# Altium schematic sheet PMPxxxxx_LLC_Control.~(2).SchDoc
size 431 x 279 mm; Date: Not shown in title block; ApprovedBy: Not shown in title block; CheckedBy: Not shown in title block; Author: Not shown in title block; CompanyName: Not shown in title block; Engineer: Not shown in title block; Organization: Not shown in title block; Address1: Not shown in title block; Address2: Not shown in title block; Address3: Not shown in title block; Address4: Not shown in title block; DocumentNumber: 1; Revision: Use project parameter SCH_Rev; SheetNumber: 4; SheetTotal: 4; PageSetup: Record=PageOptions¦CenterHorizontal=True¦CenterVertical=True¦PrintScale=1.00¦XCorrection=1.00¦YCorrection=1.00¦PrintKind=0¦BorderSize=5000000¦LeftOffset=0¦BottomOffset=0¦Orientation=2¦PaperLength=1000¦PaperWidth=1000¦Scale=100¦PaperSource=15¦PrintQuality=600¦MediaType=1¦DitherType=10¦PaperKind=Letter¦PrintScaleMode=1
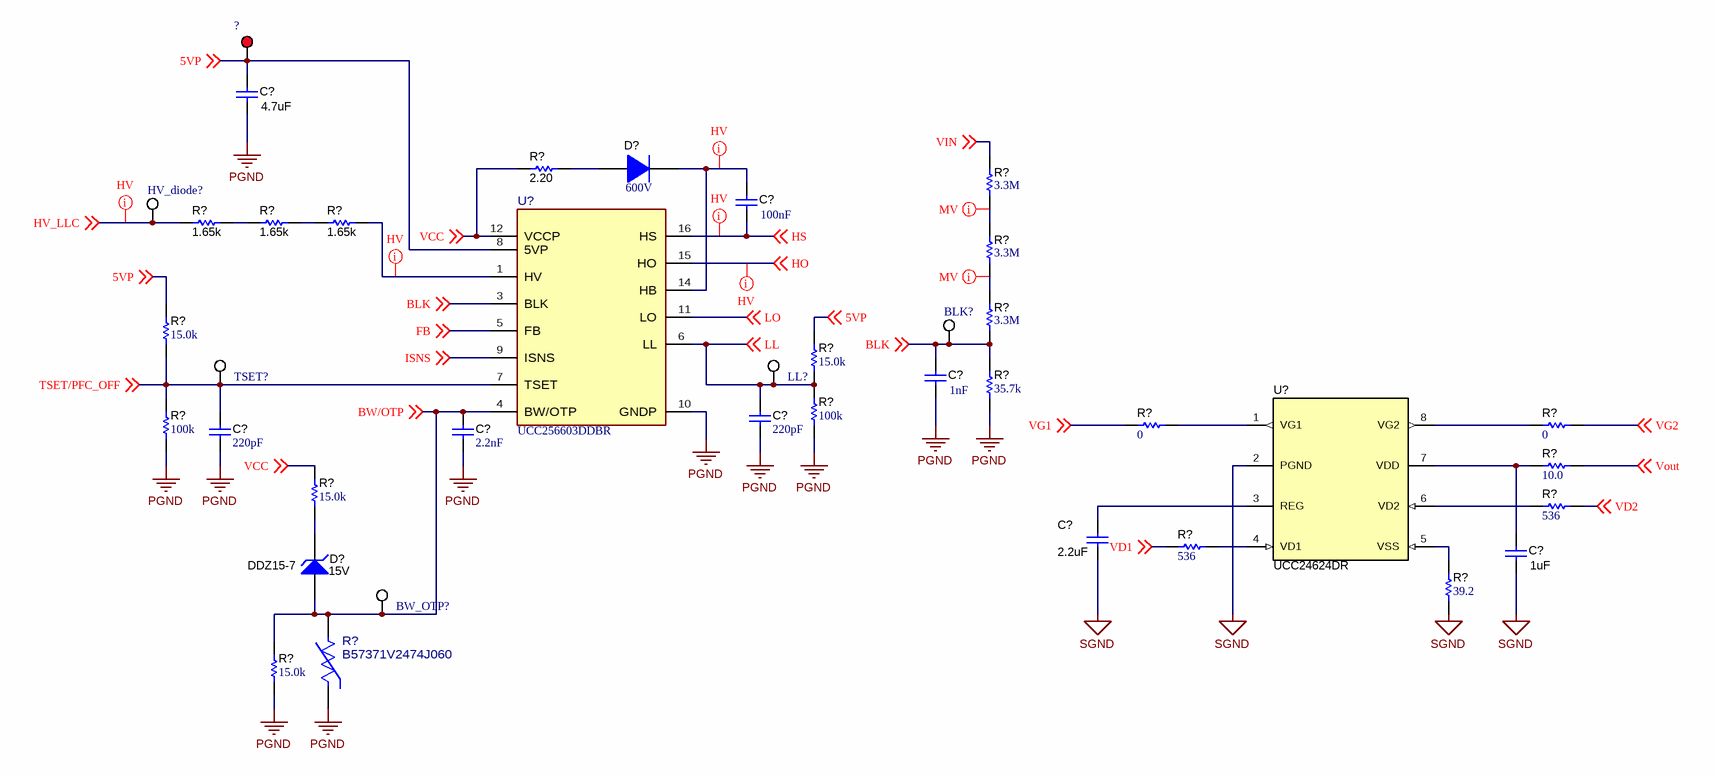
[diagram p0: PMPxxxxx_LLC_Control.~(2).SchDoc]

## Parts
(Parts that share a designator on the sheet are numbered #1, #2 ... from top to bottom, then left to right.)
?  5010  [Keystone5010]  (value not drawn)
BLK?  5012  [Keystone5012]  (value not drawn)
BW_OTP?  5012  [Keystone5012]  (value not drawn)
C?#1  ValueDisplayed: 4.7uF  [1206L]  (hidden comment: C3216X7R1E475K085AB)
C?#2  Cap_F: 100nF  [1206_180L]  (hidden comment: GRM31C5C1E104JA01L)
C?#3  Cap_F: 1nF  [0402L]  (hidden comment: 04025C102JAT2A)
C?#4  Cap_F: 220pF  [0603]  (hidden comment: C0603X221K5RACTU)
C?#5  Cap_F: 220pF  [0603]  (hidden comment: C0603X221K5RACTU)
C?#6  Cap_F: 2.2nF  [0603]  (hidden comment: C0603X222K5RACTU)
C?#7  ValueDisplayed: 2.2uF  [0805L]  (hidden comment: C2012X7R1V225K085AC)
C?#8  ValueDisplayed: 1uF  [0603L]  (hidden comment: GRM188R71C105KE15D)
D?#1  Vr_V: 600V  [SMAF]  (hidden comment: ES1JAF)
D?#2  DDZ15-7  value 15V  [SOD-123]
HV_diode?  5012  [Keystone5012]  (value not drawn)
LL?  5012  [Keystone5012]  (value not drawn)
R?#1  ValueDisplayed: 2.20  [0603L]  (hidden comment: ERJ-3RQF2R2V)
R?#2  Res_ohm: 3.3M  [FP-KTR18EZPF3304_1206-MFG]  (hidden comment: KTR18EZPF3304)
R?#3  ValueDisplayed: 1.65k  [1206L]  (hidden comment: CRCW12061K65FKEA)
R?#4  ValueDisplayed: 1.65k  [1206L]  (hidden comment: CRCW12061K65FKEA)
R?#5  ValueDisplayed: 1.65k  [1206L]  (hidden comment: CRCW12061K65FKEA)
R?#6  Res_ohm: 3.3M  [FP-KTR18EZPF3304_1206-MFG]  (hidden comment: KTR18EZPF3304)
R?#7  Res_ohm: 3.3M  [FP-KTR18EZPF3304_1206-MFG]  (hidden comment: KTR18EZPF3304)
R?#8  ValueDisplayed: 15.0k  [0603]  (hidden comment: RT0603BRD0715KL)
R?#9  ValueDisplayed: 15.0k  [0603]  (hidden comment: RT0603BRD0715KL)
R?#10  ValueDisplayed: 35.7k  [0603]  (hidden comment: RT0603BRD0735K7L)
R?#11  ValueDisplayed: 100k  [0603]  (hidden comment: RT0603BRD07100KL)
R?#12  ValueDisplayed: 100k  [0603]  (hidden comment: RT0603BRD07100KL)
R?#13  ValueDisplayed: 0  [0603L]  (hidden comment: RC0603JR-070RL)
R?#14  ValueDisplayed: 0  [0603L]  (hidden comment: RC0603JR-070RL)
R?#15  ValueDisplayed: 10.0  [0603L]  (hidden comment: RC0603FR-0710RL)
R?#16  ValueDisplayed: 15.0k  [0603]  (hidden comment: RG1608P-153-B-T5)
R?#17  ValueDisplayed: 536  [0603L]  (hidden comment: RT0603BRD07536RL)
R?#18  ValueDisplayed: 536  [0603L]  (hidden comment: RT0603BRD07536RL)
R?#19  ValueDisplayed: 39.2  [0603L]  (hidden comment: RC0603FR-0739R2L)
R?#20  ValueDisplayed: 15.0k  [0603]  (hidden comment: RG1608P-153-B-T5)
R?#21  B57371V2474J060  [FP-B57371V2474J060_0603-MFG]
TSET?  5012  [Keystone5012]  (value not drawn)
U?#1  UCC256603DDBR  [DDB0014A-MFG]
U?#2  UCC24624DR  [D0008A_N]

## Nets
PGND: C?#1.2 C?#3.2 C?#4.2 C?#5.2 C?#6.2 R?#10.1 R?#11.1 R?#12.1 R?#20.1 R?#21.1 U?#1.10(GNDP)
SGND: C?#7.2 C?#8.2 R?#19.2 U?#2.2(PGND)
5VP: ?.1 C?#1.1 R?#8.2 R?#9.2 U?#1.8(5VP) ; off-sheet 5VP
BLK: BLK?.1 C?#3.1 R?#7.1 R?#10.2 U?#1.3(BLK) ; off-sheet BLK
BW/OTP: BW_OTP?.1 C?#6.1 D?#2.2(A) R?#20.2 R?#21.2 U?#1.4(BW/OTP) ; off-sheet BW/OTP
FB: U?#1.5(FB) ; off-sheet FB
HO: U?#1.15(HO) ; off-sheet HO
HS: C?#2.2 U?#1.16(HS) ; off-sheet HS
HV_LLC: HV_diode?.1 R?#3.1 ; off-sheet HV_LLC
ISNS: U?#1.9(ISNS) ; off-sheet ISNS
LL: C?#4.1 LL?.1 R?#9.1 R?#11.2 U?#1.6(LL) ; off-sheet LL
LO: U?#1.11(LO) ; off-sheet LO
TSET/PFC_OFF: C?#5.1 R?#8.1 R?#12.2 TSET?.1 U?#1.7(TSET) ; off-sheet TSET/PFC_OFF
VCC: R?#1.1 R?#16.2 U?#1.12(VCCP) ; off-sheet VCC
VD1: R?#18.2 ; off-sheet VD1
VD2: R?#17.1 ; off-sheet VD2
VG1: R?#13.1 ; off-sheet VG1
VG2: R?#14.2 ; off-sheet VG2
VIN: R?#2.2 ; off-sheet VIN
Vout: R?#15.2 ; off-sheet Vout
NetC?#2_1: C?#2.1 D?#1.1(K) U?#1.14(HB)
NetC?#7_1: C?#7.1 U?#2.3(REG)
NetC?#8_1: C?#8.1 R?#15.1 U?#2.7(VDD)
NetD?#1_2: D?#1.2(A) R?#1.2
NetD?#2_1: D?#2.1(K) R?#16.1
NetR?#2_1: R?#2.1 R?#6.2
NetR?#3_2: R?#3.2 R?#4.1
NetR?#4_2: R?#4.2 R?#5.1
NetR?#5_2: R?#5.2 U?#1.1(HV)
NetR?#6_1: R?#6.1 R?#7.2
NetR?#13_2: R?#13.2 U?#2.1(VG1)
NetR?#14_1: R?#14.1 U?#2.8(VG2)
NetR?#17_2: R?#17.2 U?#2.6(VD2)
NetR?#18_1: R?#18.1 U?#2.4(VD1)
NetR?#19_1: R?#19.1 U?#2.5(VSS)

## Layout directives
net class MV: NetR?#2_1, NetR?#6_1
net class HV: HO, HS, HV_LLC, NetC?#2_1, NetR?#5_2

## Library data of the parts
? = CMP-0055147-2: Test Point, Multipurpose, Red, TH; Manufacturer: Keystone Electronics; CNHeader: FALSE; Green_Lifecycle: Active; Green_REACh: Passed; ContactFinish: Silver; CT: TRUE
BLK? BW_OTP? HV_diode? LL? TSET? = CMP-0055149-2: Test Point, Multipurpose, White, TH; Manufacturer: Keystone Electronics; CNHeader: FALSE; Green_Lifecycle: Active; Green_REACh: Passed; ContactFinish: Silver; CT: TRUE
C?#1 = CMP-0008693-2: CAP, CERM, 4.7 uF, 25 V, +/- 10%, X7R, 1206; Manufacturer: TDK; TaMin_C: -55°C; Polarized: N; SizeAreaWB_mm2: 10.92; Value1: Unknown; U/M: EA; Value: 4.7uF; TaMax_C: 125°C; SizeZ_mm: 1.35; SizeX_mm: 3.2; SizeY_mm: 1.6; Cap_Case: 1206; Value2: 25V; SizeArea_mm2: 5.12; CompType: Capacitor; Cap_F: 4.7µF; AEC Category: Q200
C?#2 = CMP-0064950-2: CAP, CERM, 0.1 uF, 25 V,+/- 5%, C0G/NP0, 1206; Manufacturer: MuRata; TaMin_C: -55°C; Polarized: N; SizeAreaWB_mm2: 10.92; Value1: Unknown; U/M: EA; Value: 0.1uF; TaMax_C: 125°C; SizeZ_mm: 1.8; SizeX_mm: 3.2; SizeY_mm: 1.6; Cap_Case: 1206; Value2: 25V; SizeArea_mm2: 5.12; AEC Category: Q200
C?#3 = CMP-0861060-1: CAP, CERM, 1000 pF, 50 V,+/- 5%, X7R, 0402; Manufacturer: AVX; Value2: 50V; SizeY_mm: 0.5; AEC Category: Q200; Polarized: N; Green_Lifecycle: Active; SizeAreaWB_mm2: 3; ValueDisplayed: 1000pF; Cap_Case: 0402; Value: 1000pF; TaMin_C: -55°C; U/M: EA; Green_REACh: Passed; SizeZ_mm: 0.6; SizeX_mm: 1; TaMax_C: 125°C
C?#4 C?#5 = CMP-0006982-4: CAP, CERM, 220 pF, 50 V, +/- 10%, X7R, 0603; Manufacturer: Kemet; TaMin_C: -55°C; Polarized: N; SizeAreaWB_mm2: 4.68; Value1: Unknown; U/M: EA; Value: 220pF; TaMax_C: 125°C; SizeZ_mm: 1; SizeX_mm: 1.6; SizeY_mm: 0.8; Value2: 50V; SizeArea_mm2: 1.28; AEC Category: Q200
C?#6 = CMP-0006983-4: CAP, CERM, 2200 pF, 50 V, +/- 10%, X7R, 0603; Manufacturer: Kemet; TaMin_C: -55°C; Polarized: N; SizeAreaWB_mm2: 4.68; Value1: Unknown; U/M: EA; Value: 2200pF; TaMax_C: 125°C; SizeZ_mm: 1; SizeX_mm: 1.6; SizeY_mm: 0.8; Value2: 50V; SizeArea_mm2: 1.28; AEC Category: Q200
C?#7 = CMP-0007883-2: CAP, CERM, 2.2 uF, 35 V, +/- 10%, X7R, 0805; Manufacturer: TDK; TaMin_C: -55°C; Polarized: N; SizeAreaWB_mm2: 6.75; Value1: Unknown; U/M: EA; Value: 2.2uF; TaMax_C: 125°C; SizeZ_mm: 1.45; SizeX_mm: 2; SizeY_mm: 1.25; Cap_Case: 0805; Value2: 35V; SizeArea_mm2: 2.5; CompType: Capacitor; Cap_F: 2.2µF; AEC Category: Q200
C?#8 = CMP-0007380-4: CAP, CERM, 1 uF, 16 V, +/- 10%, X7R, 0603; Manufacturer: MuRata; TaMin_C: -55°C; Polarized: N; SizeAreaWB_mm2: 4.68; Value1: Unknown; U/M: EA; Value: 1uF; TaMax_C: 125°C; SizeZ_mm: 1; SizeX_mm: 1.6; SizeY_mm: 0.8; Cap_Case: 0603; Value2: 16V; SizeArea_mm2: 1.28; CompType: Capacitor; Cap_F: 1µF; AEC Category: Q200
D?#1 = CMP-0029162-2: Diode, Ultrafast, 600 V, 1 A, AEC-Q101, SMAF; Manufacturer: Fairchild Semiconductor; Io_A: 1A; Green_Lifecycle: Not Set; SizeAreaWB_mm2: 19.95; Green_REACh: Incomplete; TJmax_C: 150°C; Value: 600V; SizeZ_mm: 1; SizeX_mm: 4.7; SizeY_mm: 2.5; Vf_V: 1.7V; SizeArea_mm2: 11.75; AEC Qualified: Y; AEC Category: Q101
D?#2 = CMP-0085135-1: Diode, Zener, 15 V, 500 mW, SOD-123; Manufacturer: Diodes Inc.; SizeAreaWB_mm2: 13.095; SizeArea_mm2: 6.545; SizeY_mm: 1.7; AEC Qualified: N; SizeZ_mm: 1.35; Value1: 0.5W; SizeX_mm: 3.85; Power_W: 500mW; RJA_CperW: 425; AEC Category: Q101
R?#1 = CMP-0022711-2: RES, 2.20, 1%, 0.1 W, 0603; Manufacturer: Panasonic; Power_W: 100mW; TempCo: 200 ppm/C; Value_Code: 2R20; U/M: EA; Value: 2.20; Res_ohm: 2.2; SizeX_mm: 1.6; SizeY_mm: 0.8; SizeZ_mm: 1; Value2: 0.1W; SizeArea_mm2: 1.28; CompType: Resistor; AEC Category: Q200
R?#2 R?#6 R?#7 = CMP-0087456-2: 3.3 MOhms ±1% 0.25W, 1/4W Chip Resistor 1206 (3216 Metric) Automotive AEC-Q200, High Voltage Thick Film; Manufacturer: Rohm Semiconductor; AEC Qualified: Yes; Power_W: 250mW; SizeZ_mm: 0.65mm; AEC Grade: Grade 0; TempCo: 100ppm/°C; VDC_V: 500V
R?#3-R?#5 = CMP-0016708-3: RES, 1.65 k, 1%, 0.25 W, AEC-Q200 Grade 0, 1206; Manufacturer: Vishay-Dale; Power_W: 250mW; TempCo: 100 ppm/C; Value_Code: 1k65; Value: 1.65k; EIA_Code: E96; SizeX_mm: 3.2; SizeY_mm: 1.6; SizeZ_mm: 1.35; Value2: 0.25W; SizeArea_mm2: 5.12; CompType: Resistor; AEC Qualified: Y; VDC_V: 200V; AEC Category: Q200; AEC Grade: 0
R?#8 R?#9 = CMP-0023780-3: RES, 15.0 k, 0.1%, 0.1 W, 0603; Manufacturer: Yageo America; Power_W: 100mW; TempCo: 25 ppm/C; Value_Code: 15k0; U/M: EA; Value: 15.0k; EIA_Code: E192; Res_ohm: 15k; SizeX_mm: 1.6; SizeY_mm: 0.8; SizeZ_mm: 1; Value2: 0.1W; SizeArea_mm2: 1.28; VDC_V: 75V; AEC Category: Q200
R?#10 = CMP-0024147-3: RES, 35.7 k, 0.1%, 0.1 W, 0603; Manufacturer: Yageo America; Power_W: 100mW; TempCo: 25 ppm/C; Value_Code: 35k7; U/M: EA; Value: 35.7k; EIA_Code: E192; SizeX_mm: 1.6; SizeY_mm: 0.8; SizeZ_mm: 1; Value2: 0.1W; SizeArea_mm2: 1.28; VDC_V: 75V; AEC Category: Q200
R?#11 R?#12 = CMP-0023630-3: RES, 100 k, 0.1%, 0.1 W, 0603; Manufacturer: Yageo America; Power_W: 100mW; TempCo: 25 ppm/C; U/M: EA; Value: 100k; EIA_Code: E192; SizeX_mm: 1.6; SizeY_mm: 0.8; SizeZ_mm: 1; Value2: 0.1W; SizeArea_mm2: 1.28; VDC_V: 75V; AEC Category: Q200
R?#13 R?#14 = CMP-0025885-5: RES, 0, 5%, 0.1 W, 0603; Manufacturer: Yageo; Power_W: 100mW; TempCo: 200 ppm/C; Value_Code: 0000; Value: 0; EIA_Code: E24; SizeX_mm: 1.6; SizeZ_mm: 1; Value2: 0.1W; SizeArea_mm2: 1.28; AEC Qualified: N; VDC_V: 75V; AEC Category: Q200; SizeY_mm: 0.8; SizeAreaWB_mm2: 4.68
R?#15 = CMP-0022751-4: RES, 10.0, 1%, 0.1 W, 0603; Manufacturer: Yageo; Power_W: 100mW; TempCo: 100 ppm/C; Value_Code: 10R0; Value: 10.0; EIA_Code: E96; Res_ohm: 10; SizeX_mm: 1.6; SizeY_mm: 0.8; SizeZ_mm: 1; Value2: 0.1W; SizeArea_mm2: 1.28; AEC Qualified: N; VDC_V: 75V; AEC Category: Q200; SizeAreaWB_mm2: 4.68
R?#16 R?#20 = CMP-0023441-3: RES, 15.0 k, 0.1%, 0.1 W, 0603; Manufacturer: Susumu Co Ltd; Power_W: 100mW; TempCo: 25 ppm/C; Value_Code: 15k0; U/M: EA; Value: 15.0k; EIA_Code: E192; Res_ohm: 15k; SizeX_mm: 1.6; SizeY_mm: 0.8; SizeZ_mm: 1; Value2: 0.1W; SizeArea_mm2: 1.28; VDC_V: 75V; AEC Category: Q200
R?#17 R?#18 = CMP-0024324-2: RES, 536, 0.1%, 0.1 W, 0603; Manufacturer: Yageo America; Power_W: 100mW; TempCo: 25 ppm/C; Value_Code: 536R; U/M: EA; Value: 536; EIA_Code: E192; SizeX_mm: 1.6; SizeY_mm: 0.8; SizeZ_mm: 1; Value2: 0.1W; SizeArea_mm2: 1.28; VDC_V: 75V; AEC Category: Q200
R?#19 = CMP-0023074-4: RES, 39.2, 1%, 0.1 W, 0603; Manufacturer: Yageo; Power_W: 100mW; TempCo: 100 ppm/C; Value_Code: 39R2; Value: 39.2; EIA_Code: E96; SizeX_mm: 1.6; SizeY_mm: 0.8; SizeZ_mm: 1; Value2: 0.1W; SizeArea_mm2: 1.28; AEC Qualified: N; VDC_V: 75V; AEC Category: Q200; SizeAreaWB_mm2: 4.68
R?#21 = CMP-0096703-1: NTC Thermistor 470k 0603 (1608 Metric); Manufacturer: TDK; AEC Qualified: No; Res_ohm: 470kΩ; Power_W: 180mW; B 25 50: 4386K; B 25 100: 4480K; SizeZ_mm: 0.9mm; B 25 85: 4455K; B Tolerance: 3%; Tolerance_%: 5%
U?#1 = CMP-0095299-1: 750kHz Wide VIN/VOUT Range LLC Controller Optimized for Light Load Efficiency; Manufacturer: Texas Instruments; Number Of Outputs: 2; TaMax_C: +125°C; Output Type: Other; TJmax_C: +150°C; AEC Qualified: No; Standoff Height: 0.1mm; TaMin_C: -40°C; SizeZ_mm: 1.75mm; Switching Frequency: 30-750kHz; Max Supply Voltage: 18.5V
U?#2 = CMP-0079610-1: High Performance Synchronous Rectifier Driver for LLC Resonant Converter, D0008A (SOIC-8); Alternate Manufacturer: Texas Instruments; SizeAreaWB_mm2: 56.58; SizeZ_mm: 1.75; SizeX_mm: 4.9; SizeY_mm: 6.2; SizeArea_mm2: 30.38; CompType: IC; AEC Qualified: N; AEC Category: Q200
